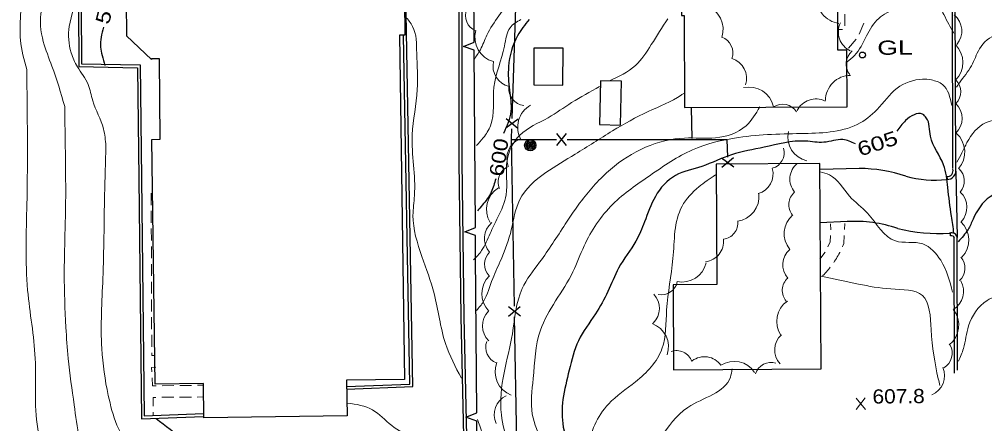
# Model space of a CAD drawing. Extents: x 2361708 to 2370558, y 6977955 to 6991887.
# Drawn here: x 2369435.4 to 2369762.2, y 6990299.4 to 6990436.3 of the extents above; entities that cross this region are included whole.
import ezdxf
from ezdxf.enums import TextEntityAlignment as Align

# ---------------------------------------------------------------- set-up
doc = ezdxf.new("R2010")
doc.units = 0
doc.header["$LTSCALE"] = 1.9
for name, color, linetype, lineweight in [('11', 7, 'Continuous', 25), ('13', 7, 'Continuous', 13), ('17', 7, 'Continuous', 25), ('18', 7, 'Continuous', 25), ('2', 7, 'Continuous', 25), ('20', 7, 'Continuous', 25), ('29', 7, 'Continuous', 13), ('31', 7, 'Continuous', 13), ('35', 7, 'Continuous', 13)]:
    doc.layers.add(name, color=color, linetype=linetype, lineweight=lineweight)

msp = doc.modelspace()

# ---------------------------------------------------------------- linework, layer by layer
at = {"layer": '11'}
for points in [[(2369660.552, 6990406.484), (2369715.593, 6990406.618), (2369715.55, 6990425.858), (2369712.46, 6990425.849), (2369712.362, 6990454.019), (2369710.722, 6990454.013), (2369710.62, 6990474.164), (2369678.02, 6990473.993), (2369678.115, 6990454.533), (2369659.405, 6990454.435), (2369659.486, 6990437.525), (2369660.486, 6990437.525)], [(2369609.527, 6990414.098), (2369619.388, 6990414.022), (2369619.489, 6990426.464), (2369609.619, 6990426.54)], [(2369632.135, 6990415.464), (2369631.806, 6990400.63), (2369638.898, 6990400.467), (2369639.237, 6990415.301)], [(2369706.807, 6990317.94), (2369706.386, 6990387.429), (2369671.286, 6990387.215), (2369671.533, 6990346.476), (2369656.683, 6990346.384), (2369656.857, 6990317.634)]]:
    msp.add_lwpolyline(points, close=True, dxfattribs=at)
for points in [[(2369499.748, 6990442.865), (2369491.553, 6990450.687), (2369479.545, 6990450.343), (2369471.572, 6990442.257), (2369471.652, 6990430.697), (2369480.199, 6990422.688)], [(2369499.748, 6990442.865), (2369499.768, 6990439.735), (2369544.167, 6990439.967), (2369544.153, 6990442.548), (2369565.793, 6990442.674), (2369565.865, 6990430.924), (2369564.134, 6990430.917)], [(2369564.134, 6990430.917), (2369565.784, 6990314.347), (2369546.166, 6990314.07), (2369546.34, 6990302.061), (2369497.904, 6990301.36), (2369497.734, 6990312.98), (2369481.455, 6990312.744), (2369480.246, 6990395.637), (2369483.156, 6990395.664), (2369482.897, 6990422.934), (2369480.197, 6990422.908), (2369480.199, 6990422.688)]]:
    msp.add_lwpolyline(points, dxfattribs=at)
at = {"layer": '13'}
for p, q in [((2369714.854, 6990438.072), (2369714.822, 6990434.072)), ((2369721.233, 6990434.983), (2369719.679, 6990431.298)), ((2369714.033, 6990432.854), (2369712.554, 6990432.85)), ((2369718.655, 6990429.608), (2369716.104, 6990426.524)), ((2369480.078, 6990373.414), (2369480.07, 6990377.414)), ((2369480.095, 6990367.414), (2369480.087, 6990371.414)), ((2369480.122, 6990361.414), (2369480.104, 6990365.414)), ((2369709.959, 6990367.052), (2369710.089, 6990365.053)), ((2369714.869, 6990367.099), (2369714.758, 6990365.098)), ((2369480.139, 6990355.414), (2369480.131, 6990359.414)), ((2369708.11, 6990357.494), (2369706.393, 6990355.047)), ((2369480.156, 6990349.414), (2369480.148, 6990353.414)), ((2369480.173, 6990343.414), (2369480.165, 6990347.414)), ((2369480.2, 6990337.414), (2369480.182, 6990341.414)), ((2369480.217, 6990331.414), (2369480.21, 6990335.414)), ((2369480.235, 6990325.413), (2369480.227, 6990329.414)), ((2369487.74, 6990312.275), (2369483.74, 6990312.227)), ((2369493.74, 6990312.341), (2369489.74, 6990312.294)), ((2369497.739, 6990312.39), (2369495.74, 6990312.371)), ((2369487.678, 6990308.343), (2369483.677, 6990308.315)), ((2369493.677, 6990308.39), (2369489.677, 6990308.362)), ((2369497.677, 6990308.429), (2369495.677, 6990308.409)), ((2369480.695, 6990303.267), (2369480.687, 6990302.057))]:
    msp.add_line(p, q, dxfattribs=at)
for points in [[(2369710.008, 6990363.053), (2369709.898, 6990360.951), (2369709.064, 6990359.243)], [(2369714.638, 6990363.097), (2369714.483, 6990360.405), (2369714.268, 6990359.873), (2369714.053, 6990359.351), (2369713.985, 6990359.2)], [(2369713.121, 6990357.402), (2369713.073, 6990357.301), (2369712.807, 6990356.799), (2369712.532, 6990356.306), (2369712.247, 6990355.813), (2369711.951, 6990355.331), (2369711.656, 6990354.848), (2369711.341, 6990354.364), (2369711.074, 6990353.972)], [(2369709.9, 6990352.351), (2369709.672, 6990352.069), (2369709.316, 6990351.625), (2369708.95, 6990351.192), (2369708.584, 6990350.768), (2369708.198, 6990350.345), (2369707.812, 6990349.931), (2369707.416, 6990349.517), (2369707.258, 6990349.355)], [(2369481.283, 6990322.453), (2369480.243, 6990322.454), (2369480.244, 6990323.414)], [(2369480.255, 6990316.953), (2369480.181, 6990318.442), (2369481.63, 6990318.516)], [(2369481.74, 6990312.197), (2369480.511, 6990312.186), (2369480.364, 6990314.954)], [(2369481.678, 6990308.296), (2369480.698, 6990308.287), (2369480.696, 6990305.267)]]:
    msp.add_lwpolyline(points, dxfattribs=at)
at = {"layer": '17'}
for p, q in [((2369602.274, 6990402.759), (2369604.214, 6990462.73)), ((2369663.202, 6990395.958), (2369662.962, 6990406.427)), ((2369604.237, 6990402.488), (2369600.136, 6990399.419)), ((2369604.137, 6990399.287), (2369600.236, 6990402.61)), ((2369602.203, 6990395.548), (2369617.204, 6990395.56)), ((2369617.402, 6990393.583), (2369620.604, 6990397.593)), ((2369620.603, 6990393.593), (2369617.404, 6990397.582)), ((2369673.095, 6990389.382), (2369677.205, 6990386.322)), ((2369673.206, 6990386.183), (2369677.094, 6990389.51)), ((2369605.032, 6990335.792), (2369600.972, 6990338.923)), ((2369604.971, 6990338.991), (2369601.032, 6990335.724))]:
    msp.add_line(p, q, dxfattribs=at)
for points in [[(2369603, 6990339.163), (2369602.058, 6990396.047), (2369602.159, 6990399.158)], [(2369620.804, 6990395.565), (2369674.856, 6990395.589), (2369675.063, 6990389.641)], [(2369604.385, 6990275.583), (2369603.768, 6990293.098), (2369603.064, 6990335.563)]]:
    msp.add_lwpolyline(points, dxfattribs=at)
at = {"layer": '18'}
for p, q in [((2369589.805, 6990365.818), (2369589.385, 6990425.817)), ((2369590.455, 6990270.28), (2369590.249, 6990300.279))]:
    msp.add_line(p, q, dxfattribs=at)
for points in [[(2369589.368, 6990428.587), (2369589.32, 6990435.787), (2369588.317, 6990488.58)], [(2369589.385, 6990425.817), (2369585.752, 6990427.113), (2369589.368, 6990428.587)], [(2369589.822, 6990363.048), (2369586.179, 6990364.344), (2369589.795, 6990365.818)], [(2369590.233, 6990303.049), (2369589.864, 6990356.549), (2369589.822, 6990363.048)], [(2369590.249, 6990300.279), (2369586.607, 6990301.575), (2369590.233, 6990303.049)]]:
    msp.add_lwpolyline(points, dxfattribs=at)
at = {"layer": '2'}
for p, q in [((2369751.383, 6990385.797), (2369751.22, 6990452.309)), ((2369752.343, 6990385.796), (2369752.18, 6990452.308)), ((2369719.661, 6990385.815), (2369706.444, 6990385.49)), ((2369749.339, 6990383.028), (2369749.489, 6990382.079)), ((2369752.431, 6990384.917), (2369752.836, 6990362.41)), ((2369715.563, 6990367.786), (2369706.506, 6990367.359)), ((2369750.631, 6990362.959), (2369750.631, 6990363.919)), ((2369751.973, 6990316.489), (2369751.876, 6990362.411)), ((2369752.933, 6990317.529), (2369752.836, 6990362.41))]:
    msp.add_line(p, q, dxfattribs=at)
for points in [[(2369582.081, 6990727.662), (2369582.84, 6990671.027), (2369583.311, 6990603.638), (2369583.802, 6990560.451), (2369583.923, 6990515.23), (2369584.226, 6990455.049), (2369584.183, 6990388.106), (2369584.874, 6990335.5), (2369586.22, 6990274.92)], [(2369583.041, 6990727.672), (2369583.8, 6990671.036), (2369584.271, 6990603.647), (2369584.762, 6990560.46), (2369584.883, 6990515.229), (2369585.186, 6990455.049), (2369585.143, 6990388.115), (2369585.834, 6990335.519), (2369587.18, 6990274.939)], [(2369546.215, 6990311.071), (2369568.607, 6990311.934), (2369566.214, 6990444.668), (2369501.886, 6990444.155), (2369501.307, 6990463.951), (2369477.512, 6990463.334)], [(2369455.418, 6990440.473), (2369455.55, 6990420.263), (2369475.425, 6990419.882), (2369475.862, 6990382.394)], [(2369456.379, 6990440.482), (2369456.502, 6990421.202), (2369476.376, 6990420.822), (2369476.822, 6990382.404)], [(2369546.206, 6990312.001), (2369567.63, 6990312.755), (2369565.506, 6990430.79)], [(2369475.862, 6990382.394), (2369476.746, 6990301.029), (2369497.79, 6990301.829)], [(2369476.822, 6990382.404), (2369477.697, 6990302.028), (2369497.751, 6990302.789)]]:
    msp.add_lwpolyline(points, dxfattribs=at)
for centre, radius, start, end in [((2369718.71, 6990330.487), 55.336, 72.34093, 89.01542), ((2369749.44, 6990385.059), 2.995, 267.30013, 14.24422), ((2369749.44, 6990385.059), 2.035, 267.30013, 14.24422), ((2369745.28, 6990417.272), 35.434, 253.97285, 276.51207), ((2369718.289, 6990323.12), 44.749, 71.15148, 93.49255), ((2369747.042, 6990424.393), 60.634, 256.3626, 273.05394), ((2369750.981, 6990362.102), 1.88, 9.42312, 112.14004), ((2369750.981, 6990362.102), 0.92, 9.42312, 112.14004)]:
    msp.add_arc(centre, radius, start, end, dxfattribs=at)
at = {"layer": '20'}
for centre, radius in [((2369720.766, 6990424.198), 1), ((2369608.361, 6990393.656), 1.9), ((2369608.361, 6990393.656), 1.442), ((2369608.361, 6990393.656), 0.973), ((2369608.361, 6990393.656), 0.539), ((2369608.361, 6990393.656), 0.192)]:
    msp.add_circle(centre, radius, dxfattribs=at)
at = {"layer": '29'}
for centre, radius, start, end in [((2369713.957, 6990443.321), 8.503, 172.38866, 262.38866), ((2369665.112, 6990432.911), 8.503, 341.17128, 71.17128), ((2369592.075, 6990437.582), 5.665, 157.44606, 247.44606), ((2369747.309, 6990432.294), 7.089, 320.34827, 50.34827), ((2369719.703, 6990432.005), 7.089, 154.43011, 244.43011), ((2369598.133, 6990430.185), 8.503, 164.54336, 254.54336), ((2369671.265, 6990424.919), 5.665, 340.31014, 70.31014), ((2369746.251, 6990421.711), 8.503, 315.19335, 45.19335), ((2369720.908, 6990421.184), 5.665, 129.31728, 219.31728), ((2369602.838, 6990420.45), 7.089, 167.19298, 257.19298), ((2369674.473, 6990416.259), 7.089, 342.14371, 72.14371), ((2369716.778, 6990408.803), 8.503, 90.13944, 180.13944), ((2369748.38, 6990411.771), 5.665, 315.19335, 45.19335), ((2369606.715, 6990412.797), 5.665, 174.32946, 264.32946), ((2369682.378, 6990404.848), 8.503, 12.50379, 102.50379), ((2369705.031, 6990402.233), 7.089, 63.70426, 153.70426), ((2369612.603, 6990399.792), 8.503, 119.41229, 209.41229), ((2369693.764, 6990401.887), 5.665, 33.18654, 123.18654), ((2369747.408, 6990402.724), 7.089, 315.19335, 45.19335), ((2369703.815, 6990396.445), 8.275, 167.22181, 257.22181), ((2369607.484, 6990389.203), 7.089, 112.46416, 202.46416), ((2369746.904, 6990391.362), 8.503, 318.45318, 48.45318), ((2369688.77, 6990391.14), 5.513, 285.87262, 15.87262), ((2369603.163, 6990381.237), 5.665, 112.89903, 202.89903), ((2369683.633, 6990383.926), 6.899, 285.87262, 15.87262), ((2369703.117, 6990382.214), 6.899, 129.86424, 219.86424), ((2369749.601, 6990381.557), 5.665, 318.50079, 48.50079), ((2369602.054, 6990371.951), 8.503, 121.34035, 211.34035), ((2369677.481, 6990376.189), 8.275, 276.77919, 6.77919), ((2369701.357, 6990373.535), 5.513, 129.86424, 219.86424), ((2369749.04, 6990372.624), 7.089, 316.65911, 46.65911), ((2369702.558, 6990363.733), 8.275, 130.09348, 220.09348), ((2369599.928, 6990362.066), 7.089, 130.6208, 220.6208), ((2369673.104, 6990367.34), 5.513, 276.4881, 6.4881), ((2369748.266, 6990361.568), 8.503, 316.65911, 46.65911), ((2369666.86, 6990361.06), 6.899, 276.4881, 6.4881), ((2369598.539, 6990353.346), 5.665, 134.00201, 224.00201), ((2369700.702, 6990353.198), 6.899, 131.06997, 221.06997), ((2369749.831, 6990352.051), 5.665, 311.59597, 41.59597), ((2369659.781, 6990355.6), 8.275, 257.77881, 347.77881), ((2369600.465, 6990343.375), 8.503, 134.10837, 224.10837), ((2369652.717, 6990348.531), 5.513, 259.07066, 349.07066), ((2369699.151, 6990344.496), 5.513, 131.27834, 221.27834), ((2369747.901, 6990344.162), 7.089, 299.93867, 29.93867), ((2369645.168, 6990338.448), 6.899, 313.60642, 43.60642), ((2369700.041, 6990334.01), 8.275, 124.0956, 214.0956), ((2369599.269, 6990332.473), 7.089, 135.35036, 225.35036), ((2369744.871, 6990332.775), 8.503, 307.75261, 37.75261), ((2369646.856, 6990325.455), 8.275, 340.71579, 70.71579), ((2369697.993, 6990324.325), 6.899, 132.16411, 222.16411), ((2369598.957, 6990325.247), 5.665, 159.19022, 249.19022), ((2369657.862, 6990318.598), 5.513, 19.82322, 109.82322), ((2369745.494, 6990323.232), 5.665, 299.95798, 29.95798), ((2369604.945, 6990317.033), 8.503, 159.19022, 249.19022), ((2369667.303, 6990315.143), 6.899, 36.4698, 126.4698), ((2369677.357, 6990312.211), 8.275, 33.07998, 123.07998), ((2369689.875, 6990314.61), 5.513, 72.95067, 162.95067), ((2369741.482, 6990315.662), 7.089, 292.93667, 22.93667), ((2369603.25, 6990302.481), 7.089, 115.80358, 205.80358)]:
    msp.add_arc(centre, radius, start, end, dxfattribs=at)
at = {"layer": '31'}
for p, q in [((2369721.768, 6990304.221), (2369718.652, 6990308.072)), ((2369718.688, 6990304.192), (2369721.731, 6990308.102))]:
    msp.add_line(p, q, dxfattribs=at)
at = {"layer": '31', "lineweight": 25}
for points in [[(2369607.946, 6990436.255), (2369604.058, 6990430.717), (2369601.008, 6990420.307), (2369601.334, 6990412.28), (2369601.782, 6990405.164), (2369599.343, 6990397.671)], [(2369463.874, 6990433.593), (2369462.888, 6990426.903), (2369463.415, 6990424.078), (2369464.427, 6990420.657)], [(2369751.752, 6990363.88), (2369750.916, 6990369.672), (2369749.664, 6990379.341), (2369748.241, 6990387.017), (2369743.789, 6990396.676), (2369742.399, 6990402.972), (2369741.148, 6990404.151), (2369735.408, 6990401.986), (2369732.452, 6990398.458)], [(2369718.382, 6990394.123), (2369714.168, 6990395.563), (2369707.737, 6990394.642), (2369701.522, 6990395.043), (2369687.512, 6990392.95), (2369676.495, 6990390.445), (2369666.383, 6990386.478), (2369657.511, 6990383.404), (2369650.688, 6990376.328), (2369647.031, 6990367.673), (2369644.092, 6990361.164), (2369638.269, 6990352.079), (2369634.634, 6990344.114), (2369630.436, 6990336.584), (2369624.662, 6990327.448), (2369621.547, 6990317.508), (2369619.431, 6990307.558), (2369619.53, 6990298.248), (2369622.74, 6990287.758), (2369624.411, 6990281.393), (2369625.955, 6990272.578), (2369627.866, 6990261.926), (2369628.541, 6990251.921), (2369629.609, 6990243.751), (2369630.781, 6990238.282)], [(2369596.65, 6990382.254), (2369595.162, 6990377.77), (2369592.134, 6990373.361), (2369590.443, 6990371.395)], [(2369783.171, 6990361.998), (2369778.532, 6990370.245), (2369773.938, 6990375.911), (2369769.239, 6990377.867), (2369763.955, 6990376.196), (2369758.217, 6990368.621), (2369756.52, 6990365.125), (2369753.12, 6990360.962)], [(2369481.696, 6990301.106), (2369491.214, 6990294.016), (2369499.61, 6990288.236), (2369509.115, 6990282.396), (2369515.352, 6990277.535), (2369518.471, 6990270.305), (2369518.616, 6990269.766)]]:
    msp.add_spline(points, degree=3, dxfattribs=at)
at = {"layer": '35'}
for points in [[(2369583.159, 6990623.878), (2369578.06, 6990607.968), (2369574.274, 6990592.842), (2369565.841, 6990581.521), (2369559.181, 6990565.697), (2369551.033, 6990552.878), (2369540.701, 6990539.39), (2369528.116, 6990527.279), (2369518.052, 6990517.083), (2369500.373, 6990501.194), (2369482.065, 6990487.219), (2369463.867, 6990474.335), (2369452.353, 6990461.995), (2369447.533, 6990450.418), (2369442.928, 6990439.404), (2369443.549, 6990428.729), (2369446.468, 6990420.457), (2369450.809, 6990406.727)], [(2369552.918, 6990621.749), (2369552.801, 6990606.668), (2369548.551, 6990591.977), (2369538.876, 6990577.714), (2369530.469, 6990562.653), (2369519.773, 6990546.42), (2369508.104, 6990534.689), (2369497.308, 6990526.876), (2369484.683, 6990513.685), (2369469.921, 6990494.834), (2369454.73, 6990478.088), (2369441.917, 6990466.826), (2369436.714, 6990449.215), (2369435.875, 6990437.596), (2369435.795, 6990429.206), (2369437.929, 6990419.255)], [(2369583.549, 6990558.768), (2369576.774, 6990549.703), (2369566.944, 6990538.139), (2369559.496, 6990532.608), (2369548.031, 6990516.268), (2369533.802, 6990502.522), (2369517.201, 6990490.953), (2369500.632, 6990480.245), (2369490.788, 6990473.291), (2369479.824, 6990468.417), (2369475.74, 6990466.708), (2369463.318, 6990462.539), (2369455.666, 6990453.256), (2369455.001, 6990445.439), (2369452.331, 6990433.903), (2369452.966, 6990424.959), (2369455.071, 6990420.248), (2369458.708, 6990414.253), (2369460.271, 6990408.738), (2369463.921, 6990399.222), (2369464.717, 6990393.379)], [(2369608.339, 6990447.529), (2369607.411, 6990447.24), (2369602.396, 6990443.562), (2369597.754, 6990437.478), (2369593.656, 6990430.938), (2369591.473, 6990425.987), (2369589.245, 6990422.636)], [(2369751.667, 6990431.632), (2369748.317, 6990437.921), (2369745.357, 6990442.103), (2369740.143, 6990442.473), (2369731.928, 6990439.865), (2369726.318, 6990436.591), (2369722.144, 6990430.681), (2369718.058, 6990423.982), (2369715.558, 6990421.858)], [(2369585.061, 6990314.781), (2369579.679, 6990326.49), (2369575.798, 6990343.474), (2369571.688, 6990355.956), (2369568.665, 6990369.917), (2369569.172, 6990376.592), (2369568.415, 6990397.226), (2369570.13, 6990412.503), (2369569.923, 6990424.812), (2369568.556, 6990433.869), (2369566.064, 6990437.236)], [(2369605.186, 6990436.228), (2369601.542, 6990433.453), (2369599.632, 6990427.215), (2369596.073, 6990413.321), (2369594.878, 6990400.228), (2369592.456, 6990396.175), (2369590.172, 6990393.534)], [(2369654.886, 6990436.471), (2369649.319, 6990427.718), (2369643.936, 6990420.626), (2369635.135, 6990415.422)], [(2369782.728, 6990410.687), (2369779.151, 6990416.683), (2369774.871, 6990423.953), (2369771.228, 6990429.488), (2369766.334, 6990430.912), (2369760.428, 6990426.275), (2369757.682, 6990420.569), (2369753.608, 6990414.77), (2369752.572, 6990413.28)], [(2369427.813, 6990429.3), (2369426.317, 6990412.075), (2369424.58, 6990383.426), (2369426.735, 6990361.916), (2369428.134, 6990335.728), (2369429.465, 6990315.64), (2369430.629, 6990300.51), (2369432.606, 6990286.198), (2369435.671, 6990276.157), (2369439.19, 6990266.87), (2369442.297, 6990255.609), (2369446.21, 6990244.876), (2369450.612, 6990235.227), (2369451.116, 6990230.582), (2369446.008, 6990221.913), (2369444.572, 6990210.978), (2369445.798, 6990203.04), (2369448.261, 6990192.183), (2369450.238, 6990179.971), (2369451.617, 6990164.283), (2369452.35, 6990147.149), (2369454.267, 6990125.387), (2369457.314, 6990106.825), (2369459.995, 6990082.619), (2369461.595, 6990061.614), (2369465.029, 6990045.455), (2369469.011, 6990029.442), (2369470.339, 6990012.834), (2369470.284, 6990007.083)], [(2369437.929, 6990419.255), (2369438.121, 6990403.347), (2369438.002, 6990373.864), (2369438.25, 6990344.555), (2369440.81, 6990321.438), (2369441.942, 6990296.108), (2369446.681, 6990280.422), (2369451.019, 6990267.062), (2369459.409, 6990256.532), (2369462.036, 6990245.346), (2369466.975, 6990237.053), (2369468.33, 6990231.345), (2369462.699, 6990223.992), (2369456.44, 6990215.472), (2369456.224, 6990206.629), (2369459, 6990192.355), (2369460.08, 6990174.484), (2369461.35, 6990156.596), (2369462.738, 6990137.888), (2369464.314, 6990115.262), (2369467.151, 6990100.938), (2369471.263, 6990087.056), (2369475.94, 6990073.781), (2369481.379, 6990061.232), (2369483.241, 6990049.549), (2369484.54, 6990034.9), (2369484.611, 6990024.241)], [(2369751, 6990407.125), (2369747.923, 6990414.196), (2369744.137, 6990415.75), (2369741.075, 6990416.011), (2369732.494, 6990412.959), (2369725.743, 6990405.724), (2369719.05, 6990400.701), (2369699.938, 6990397.628), (2369677.472, 6990396.074), (2369663.289, 6990392.119), (2369648.891, 6990383.432), (2369636.313, 6990373.691), (2369626.587, 6990359.578), (2369622.82, 6990350.812), (2369611.778, 6990330.986), (2369609.324, 6990314.651), (2369609.048, 6990302.649), (2369612.241, 6990292.798), (2369614.9, 6990279.273), (2369615.778, 6990268.001), (2369620.274, 6990256.923), (2369624.118, 6990248.079), (2369625.568, 6990240.733), (2369626.996, 6990235.686)], [(2369631.834, 6990413.501), (2369622.355, 6990408.09), (2369614.393, 6990402.974), (2369604.759, 6990397.002), (2369600.51, 6990388.492), (2369600.201, 6990376.838), (2369597.403, 6990369.271), (2369594.766, 6990363.736), (2369591.89, 6990357.998), (2369589.14, 6990354.811)], [(2369660.287, 6990411.221), (2369659.472, 6990410.643), (2369648.285, 6990405.057), (2369636.206, 6990398.512), (2369623.581, 6990390.621), (2369613.58, 6990384.376), (2369604.738, 6990375.091), (2369601.934, 6990365.004), (2369598.577, 6990355.201), (2369595.651, 6990348.483), (2369592.514, 6990340.723), (2369590.144, 6990337.65)], [(2369450.809, 6990406.727), (2369450.967, 6990394.318), (2369451.081, 6990371.928), (2369450.638, 6990350.153), (2369451.2, 6990331.997), (2369451.951, 6990321.484), (2369454.011, 6990305.723), (2369455.828, 6990294.489), (2369459.744, 6990284.377), (2369465.882, 6990275.164), (2369473.37, 6990263.885), (2369479.351, 6990255.432), (2369484.048, 6990242.086), (2369489.578, 6990233.698), (2369487.457, 6990228.597), (2369481.896, 6990225.525), (2369473.967, 6990220.099), (2369471.248, 6990210.542), (2369470.52, 6990199.775), (2369471.095, 6990187.7), (2369471.914, 6990173.187), (2369472.747, 6990154.934), (2369474.689, 6990134.792), (2369475.348, 6990116.957), (2369476.573, 6990100.738), (2369480.216, 6990088.942), (2369485.077, 6990082.498), (2369490.433, 6990079.828), (2369493.366, 6990079.516)], [(2369686.052, 6990406.617), (2369681.422, 6990400.272), (2369671.101, 6990396.144), (2369660.601, 6990396.094), (2369647.4, 6990392.958), (2369635.511, 6990385.465), (2369625.8, 6990374.992), (2369620.206, 6990366.918), (2369611.528, 6990354.075), (2369605.613, 6990345.118), (2369602.309, 6990329.846), (2369599.504, 6990316.638), (2369598.579, 6990302.419), (2369600.684, 6990292.508), (2369602.621, 6990280.226), (2369603.81, 6990269.847), (2369607.814, 6990261.025), (2369614.378, 6990256.387), (2369621.117, 6990240.81)], [(2369782.995, 6990380.518), (2369778.356, 6990391.885), (2369774.199, 6990397.915), (2369768.431, 6990401.9), (2369762.616, 6990401.305), (2369756.159, 6990394.603), (2369754.463, 6990391.107), (2369752.703, 6990387.87)], [(2369464.717, 6990393.379), (2369464.295, 6990376.804), (2369463.704, 6990348.577), (2369463.339, 6990324.843), (2369465.541, 6990308.953), (2369468.476, 6990298.93), (2369472.226, 6990291.616), (2369478.035, 6990283.32), (2369486.026, 6990274.906), (2369496.473, 6990260.575), (2369504.491, 6990248.201), (2369510.01, 6990239.923), (2369514.047, 6990232.911), (2369509.057, 6990230.733), (2369501.876, 6990225.575), (2369494.177, 6990222.331), (2369486.809, 6990217.861), (2369481.296, 6990210.798), (2369479.803, 6990200.583), (2369481.037, 6990186.514), (2369482.621, 6990171.399), (2369482.929, 6990155.831), (2369483.923, 6990137.529), (2369484.392, 6990119.773), (2369485.445, 6990102.702), (2369486.669, 6990094.864), (2369490.431, 6990089.489), (2369492.604, 6990088.14), (2369493.096, 6990087.894)], [(2369671.03, 6990383.602), (2369665.418, 6990379.559), (2369659.73, 6990373.015), (2369656.658, 6990355.314), (2369654.504, 6990337.923), (2369652.939, 6990324.727), (2369643.975, 6990313.551), (2369634.837, 6990306.034), (2369628.001, 6990290.888), (2369629.323, 6990277.961), (2369634.121, 6990259.385), (2369637.91, 6990244.8), (2369643.073, 6990232.889), (2369647.972, 6990221.475), (2369650.363, 6990217.197)], [(2369751.302, 6990343.935), (2369747.259, 6990354.686), (2369741.206, 6990360.229), (2369731.916, 6990361.25), (2369722.506, 6990370.622), (2369716.39, 6990376.424), (2369709.622, 6990383.62), (2369706.432, 6990384.66)], [(2369747.012, 6990312.282), (2369746.451, 6990314.607), (2369744.012, 6990331.214), (2369741.092, 6990342.827), (2369730.42, 6990344.996), (2369719.464, 6990346.651), (2369706.798, 6990349.351)], [(2369775.246, 6990337.272), (2369769.053, 6990342.773), (2369762.999, 6990341.106), (2369756.711, 6990332.456), (2369754.953, 6990324.838), (2369753.275, 6990320.542)], [(2369676.655, 6990317.942), (2369676.092, 6990315.127), (2369661.659, 6990304.88), (2369652.348, 6990294.44), (2369647.75, 6990286.876), (2369645.673, 6990273.845), (2369644.323, 6990262.342), (2369645.451, 6990247.892), (2369648.426, 6990234.7), (2369654.494, 6990224.457), (2369655.54, 6990222.817)], [(2369546.489, 6990306.363), (2369554.951, 6990304.093), (2369561.452, 6990298.745), (2369567.909, 6990293.906), (2369567.155, 6990268.098), (2369570.068, 6990259.325), (2369571.115, 6990245.994), (2369574.93, 6990239.16)], [(2369602.054, 6990259.96), (2369600.712, 6990265.347), (2369599.733, 6990271.548), (2369593.746, 6990284.842), (2369592.986, 6990292.195), (2369590.484, 6990300.802)]]:
    msp.add_spline(points, degree=3, dxfattribs=at)

# ---------------------------------------------------------------- texts
at = {"layer": '20', "width": 1.4}
msp.add_text('  GL', height=4.8, rotation=0.545, dxfattribs=at).set_placement((2369720.836, 6990424.198))
at = {"layer": '31'}
for s, rotation, width, p in [(' 590 ', 75.65, 1.25, (2369467.388, 6990440.767)), (' 605 ', 18.033, 1.3, (2369726.601, 6990391.96)), (' 600 ', 81.809, 1.2, (2369600.114, 6990389.217))]:
    msp.add_text(s, height=4.8, rotation=rotation, dxfattribs=dict(at, width=width)).set_placement(p, align=Align.CENTER)
at = {"layer": '31', "width": 1.1}
msp.add_text('607.8', height=4.8, rotation=0.545, dxfattribs=at).set_placement((2369724.21, 6990306.185))

doc.saveas('drawing.dxf')
